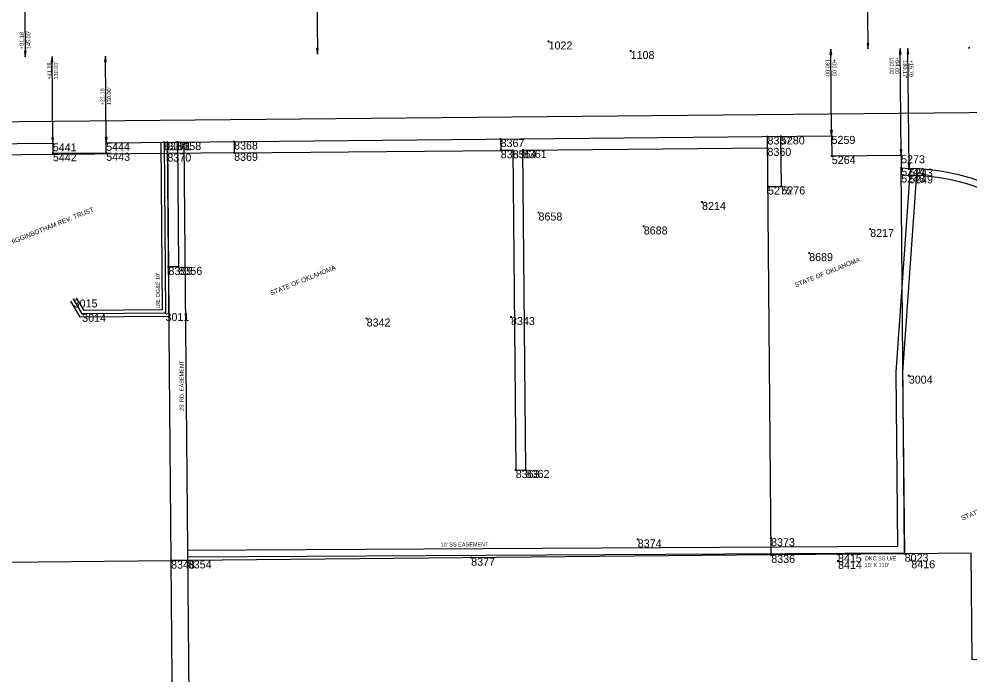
# Model space of a CAD drawing. Extents: x 2145146 to 2158053, y 137507 to 150829.
# Drawn here: x 2148600 to 2150026, y 142146 to 143129 of the extents above; entities that cross this region are included whole.
import ezdxf

# ---------------------------------------------------------------- set-up
doc = ezdxf.new("R2010")
doc.units = 0
for name, color, linetype in [('ALIGN_Cogo Points', 7, 'Continuous'), ('ALIGN_ROW Dimension', 7, 'Continuous'), ('ALIGN_ROW Line', 7, 'Continuous'), ('PLSS_Easement', 7, 'Continuous'), ('PLSS_Property Line', 7, 'Continuous'), ('PLSS_Section Line', 7, 'Continuous'), ('PLSS_Text', 7, 'Continuous'), ('PLSS_Text_TURNED OFF', 7, 'Continuous')]:
    doc.layers.add(name, color=color, linetype=linetype)

# ---------------------------------------------------------------- blocks, each defined once
blk = doc.blocks.new('Arrowhd')
at = {"layer": 'PLSS_Property Line'}
blk.add_lwpolyline([(0.125, -0.021), (0.125, 0.021), (0, 0)], close=True, dxfattribs=at)

msp = doc.modelspace()

# ---------------------------------------------------------------- linework, layer by layer
at = {"layer": 'ALIGN_Cogo Points'}
for points in [[(2149393.7, 143095.3), (2149393.7, 143096.5), (2149393.7, 143095.3), (2149392.5, 143095.3), (2149393.7, 143095.3), (2149393.7, 143094.1), (2149393.7, 143095.3), (2149394.9, 143095.3)], [(2149516.8, 143081), (2149516.8, 143082.2), (2149516.8, 143081), (2149515.6, 143081), (2149516.8, 143081), (2149516.8, 143079.8), (2149516.8, 143081), (2149518, 143081)], [(2150024.3, 143085.8), (2150024.3, 143087), (2150024.3, 143085.8), (2150023.1, 143085.8), (2150024.3, 143085.8), (2150024.3, 143084.6), (2150024.3, 143085.8), (2150025.5, 143085.8)], [(2149321.7, 142949.1), (2149321.7, 142950.3), (2149321.7, 142949.1), (2149320.5, 142949.1), (2149321.7, 142949.1), (2149321.7, 142947.9), (2149321.7, 142949.1), (2149322.9, 142949.1)], [(2149722, 142952.9), (2149722, 142954.1), (2149722, 142952.9), (2149720.8, 142952.9), (2149722, 142952.9), (2149722, 142951.7), (2149722, 142952.9), (2149723.2, 142952.9)], [(2149742, 142953.1), (2149742, 142954.3), (2149742, 142953.1), (2149740.8, 142953.1), (2149742, 142953.1), (2149742, 142951.9), (2149742, 142953.1), (2149743.2, 142953.1)], [(2149818, 142953.8), (2149818, 142955), (2149818, 142953.8), (2149816.8, 142953.8), (2149818, 142953.8), (2149818, 142952.6), (2149818, 142953.8), (2149819.2, 142953.8)], [(2148650.3, 142942.7), (2148650.3, 142943.9), (2148650.3, 142942.7), (2148649.1, 142942.7), (2148650.3, 142942.7), (2148650.3, 142941.5), (2148650.3, 142942.7), (2148651.5, 142942.7)], [(2148730.3, 142943.5), (2148730.3, 142944.7), (2148730.3, 142943.5), (2148729.1, 142943.5), (2148730.3, 142943.5), (2148730.3, 142942.3), (2148730.3, 142943.5), (2148731.5, 142943.5)], [(2148817.1, 142944.4), (2148817.1, 142945.6), (2148817.1, 142944.4), (2148815.9, 142944.4), (2148817.1, 142944.4), (2148817.1, 142943.2), (2148817.1, 142944.4), (2148818.3, 142944.4)], [(2148822.1, 142944.4), (2148822.1, 142945.6), (2148822.1, 142944.4), (2148820.9, 142944.4), (2148822.1, 142944.4), (2148822.1, 142943.2), (2148822.1, 142944.4), (2148823.3, 142944.4)], [(2148837.1, 142944.6), (2148837.1, 142945.8), (2148837.1, 142944.6), (2148835.9, 142944.6), (2148837.1, 142944.6), (2148837.1, 142943.4), (2148837.1, 142944.6), (2148838.3, 142944.6)], [(2148922.1, 142945.4), (2148922.1, 142946.6), (2148922.1, 142945.4), (2148920.9, 142945.4), (2148922.1, 142945.4), (2148922.1, 142944.2), (2148922.1, 142945.4), (2148923.3, 142945.4)], [(2149321.9, 142932.2), (2149321.9, 142933.4), (2149321.9, 142932.2), (2149320.7, 142932.2), (2149321.9, 142932.2), (2149321.9, 142931), (2149321.9, 142932.2), (2149323.1, 142932.2)], [(2149340.1, 142932.3), (2149340.1, 142933.5), (2149340.1, 142932.3), (2149338.9, 142932.3), (2149340.1, 142932.3), (2149340.1, 142931.1), (2149340.1, 142932.3), (2149341.3, 142932.3)], [(2149355.1, 142932.5), (2149355.1, 142933.7), (2149355.1, 142932.5), (2149353.9, 142932.5), (2149355.1, 142932.5), (2149355.1, 142931.3), (2149355.1, 142932.5), (2149356.3, 142932.5)], [(2149721.9, 142935.9), (2149721.9, 142937.1), (2149721.9, 142935.9), (2149720.7, 142935.9), (2149721.9, 142935.9), (2149721.9, 142934.7), (2149721.9, 142935.9), (2149723.1, 142935.9)], [(2148650.5, 142927.7), (2148650.5, 142928.9), (2148650.5, 142927.7), (2148649.3, 142927.7), (2148650.5, 142927.7), (2148650.5, 142926.5), (2148650.5, 142927.7), (2148651.7, 142927.7)], [(2148730.4, 142928.5), (2148730.4, 142929.7), (2148730.4, 142928.5), (2148729.2, 142928.5), (2148730.4, 142928.5), (2148730.4, 142927.3), (2148730.4, 142928.5), (2148731.6, 142928.5)], [(2148822.2, 142927.4), (2148822.2, 142928.6), (2148822.2, 142927.4), (2148821, 142927.4), (2148822.2, 142927.4), (2148822.2, 142926.2), (2148822.2, 142927.4), (2148823.4, 142927.4)], [(2148922.2, 142928.4), (2148922.2, 142929.6), (2148922.2, 142928.4), (2148921, 142928.4), (2148922.2, 142928.4), (2148922.2, 142927.2), (2148922.2, 142928.4), (2148923.4, 142928.4)], [(2149818.3, 142923.8), (2149818.3, 142925), (2149818.3, 142923.8), (2149817.1, 142923.8), (2149818.3, 142923.8), (2149818.3, 142922.6), (2149818.3, 142923.8), (2149819.5, 142923.8)], [(2149922.3, 142924.8), (2149922.3, 142926), (2149922.3, 142924.8), (2149921.1, 142924.8), (2149922.3, 142924.8), (2149922.3, 142923.6), (2149922.3, 142924.8), (2149923.5, 142924.8)], [(2149922.4, 142905.9), (2149922.4, 142907.1), (2149922.4, 142905.9), (2149921.2, 142905.9), (2149922.4, 142905.9), (2149922.4, 142904.7), (2149922.4, 142905.9), (2149923.6, 142905.9)], [(2149934.2, 142904.7), (2149934.2, 142905.9), (2149934.2, 142904.7), (2149933, 142904.7), (2149934.2, 142904.7), (2149934.2, 142903.5), (2149934.2, 142904.7), (2149935.4, 142904.7)], [(2149922.5, 142895.9), (2149922.5, 142897.1), (2149922.5, 142895.9), (2149921.3, 142895.9), (2149922.5, 142895.9), (2149922.5, 142894.7), (2149922.5, 142895.9), (2149923.7, 142895.9)], [(2149934.3, 142894.7), (2149934.3, 142895.9), (2149934.3, 142894.7), (2149933.1, 142894.7), (2149934.3, 142894.7), (2149934.3, 142893.5), (2149934.3, 142894.7), (2149935.5, 142894.7)], [(2149722.7, 142877.9), (2149722.7, 142879.1), (2149722.7, 142877.9), (2149721.5, 142877.9), (2149722.7, 142877.9), (2149722.7, 142876.7), (2149722.7, 142877.9), (2149723.9, 142877.9)], [(2149742.7, 142878.1), (2149742.7, 142879.3), (2149742.7, 142878.1), (2149741.5, 142878.1), (2149742.7, 142878.1), (2149742.7, 142876.9), (2149742.7, 142878.1), (2149743.9, 142878.1)], [(2149623.8, 142854.8), (2149623.8, 142856), (2149623.8, 142854.8), (2149622.6, 142854.8), (2149623.8, 142854.8), (2149623.8, 142853.6), (2149623.8, 142854.8), (2149625, 142854.8)], [(2149378.6, 142839), (2149378.6, 142840.2), (2149378.6, 142839), (2149377.4, 142839), (2149378.6, 142839), (2149378.6, 142837.8), (2149378.6, 142839), (2149379.8, 142839)], [(2149536.4, 142818.1), (2149536.4, 142819.3), (2149536.4, 142818.1), (2149535.2, 142818.1), (2149536.4, 142818.1), (2149536.4, 142816.9), (2149536.4, 142818.1), (2149537.6, 142818.1)], [(2149875.9, 142814.3), (2149875.9, 142815.5), (2149875.9, 142814.3), (2149874.7, 142814.3), (2149875.9, 142814.3), (2149875.9, 142813.1), (2149875.9, 142814.3), (2149877.1, 142814.3)], [(2149784.4, 142778.2), (2149784.4, 142779.4), (2149784.4, 142778.2), (2149783.2, 142778.2), (2149784.4, 142778.2), (2149784.4, 142777), (2149784.4, 142778.2), (2149785.6, 142778.2)], [(2148823.7, 142757.4), (2148823.7, 142758.6), (2148823.7, 142757.4), (2148822.5, 142757.4), (2148823.7, 142757.4), (2148823.7, 142756.2), (2148823.7, 142757.4), (2148824.9, 142757.4)], [(2148838.7, 142757.6), (2148838.7, 142758.8), (2148838.7, 142757.6), (2148837.5, 142757.6), (2148838.7, 142757.6), (2148838.7, 142756.4), (2148838.7, 142757.6), (2148839.9, 142757.6)], [(2148681.6, 142708.7), (2148681.6, 142709.9), (2148681.6, 142708.7), (2148680.4, 142708.7), (2148681.6, 142708.7), (2148681.6, 142707.5), (2148681.6, 142708.7), (2148682.8, 142708.7)], [(2148694.4, 142687.2), (2148694.4, 142688.4), (2148694.4, 142687.2), (2148693.2, 142687.2), (2148694.4, 142687.2), (2148694.4, 142686), (2148694.4, 142687.2), (2148695.6, 142687.2)], [(2148819.3, 142688.4), (2148819.3, 142689.6), (2148819.3, 142688.4), (2148818.1, 142688.4), (2148819.3, 142688.4), (2148819.3, 142687.2), (2148819.3, 142688.4), (2148820.5, 142688.4)], [(2149120.9, 142680.2), (2149120.9, 142681.4), (2149120.9, 142680.2), (2149119.7, 142680.2), (2149120.9, 142680.2), (2149120.9, 142679), (2149120.9, 142680.2), (2149122.1, 142680.2)], [(2149337.4, 142682.3), (2149337.4, 142683.5), (2149337.4, 142682.3), (2149336.2, 142682.3), (2149337.4, 142682.3), (2149337.4, 142681.1), (2149337.4, 142682.3), (2149338.6, 142682.3)], [(2149933.8, 142594.6), (2149933.8, 142595.8), (2149933.8, 142594.6), (2149932.6, 142594.6), (2149933.8, 142594.6), (2149933.8, 142593.4), (2149933.8, 142594.6), (2149935, 142594.6)], [(2149344.4, 142453.1), (2149344.4, 142454.3), (2149344.4, 142453.1), (2149343.2, 142453.1), (2149344.4, 142453.1), (2149344.4, 142451.9), (2149344.4, 142453.1), (2149345.6, 142453.1)], [(2149359.4, 142453.3), (2149359.4, 142454.5), (2149359.4, 142453.3), (2149358.2, 142453.3), (2149359.4, 142453.3), (2149359.4, 142452.1), (2149359.4, 142453.3), (2149360.6, 142453.3)], [(2149527.4, 142349.1), (2149527.4, 142350.3), (2149527.4, 142349.1), (2149526.2, 142349.1), (2149527.4, 142349.1), (2149527.4, 142347.9), (2149527.4, 142349.1), (2149528.6, 142349.1)], [(2149727.3, 142351), (2149727.3, 142352.2), (2149727.3, 142351), (2149726.1, 142351), (2149727.3, 142351), (2149727.3, 142349.8), (2149727.3, 142351), (2149728.5, 142351)], [(2149277.6, 142321.7), (2149277.6, 142322.9), (2149277.6, 142321.7), (2149276.4, 142321.7), (2149277.6, 142321.7), (2149277.6, 142320.5), (2149277.6, 142321.7), (2149278.8, 142321.7)], [(2149727.6, 142326), (2149727.6, 142327.2), (2149727.6, 142326), (2149726.4, 142326), (2149727.6, 142326), (2149727.6, 142324.8), (2149727.6, 142326), (2149728.8, 142326)], [(2149827.6, 142326.9), (2149827.6, 142328.1), (2149827.6, 142326.9), (2149826.4, 142326.9), (2149827.6, 142326.9), (2149827.6, 142325.7), (2149827.6, 142326.9), (2149828.8, 142326.9)], [(2149927.6, 142327.8), (2149927.6, 142329), (2149927.6, 142327.8), (2149926.4, 142327.8), (2149927.6, 142327.8), (2149927.6, 142326.6), (2149927.6, 142327.8), (2149928.8, 142327.8)], [(2148827.7, 142317.4), (2148827.7, 142318.6), (2148827.7, 142317.4), (2148826.5, 142317.4), (2148827.7, 142317.4), (2148827.7, 142316.2), (2148827.7, 142317.4), (2148828.9, 142317.4)], [(2148852.7, 142317.7), (2148852.7, 142318.9), (2148852.7, 142317.7), (2148851.5, 142317.7), (2148852.7, 142317.7), (2148852.7, 142316.5), (2148852.7, 142317.7), (2148853.9, 142317.7)], [(2149827.7, 142316.9), (2149827.7, 142318.1), (2149827.7, 142316.9), (2149826.5, 142316.9), (2149827.7, 142316.9), (2149827.7, 142315.7), (2149827.7, 142316.9), (2149828.9, 142316.9)], [(2149937.6, 142317.9), (2149937.6, 142319.1), (2149937.6, 142317.9), (2149936.4, 142317.9), (2149937.6, 142317.9), (2149937.6, 142316.7), (2149937.6, 142317.9), (2149938.8, 142317.9)]]:
    msp.add_lwpolyline(points, dxfattribs=at)
at = {"layer": 'ALIGN_ROW Dimension'}
for points in [[(2149868, 143567.3), (2149872.6, 143084.3)], [(2149045.2, 143275.5), (2149047.1, 143076.5)], [(2148607.7, 143217.4), (2148609.1, 143072.4)], [(2149818, 142953.8), (2149816.8, 143083.8)], [(2149922.3, 142924.8), (2149920.8, 143084.8)], [(2149934.2, 142904.7), (2149932.5, 143084.9)], [(2148650.3, 142942.7), (2148649.1, 143072.7)], [(2148730.3, 142943.5), (2148729.1, 143073.5)]]:
    msp.add_lwpolyline(points, dxfattribs=at)
at = {"layer": 'ALIGN_ROW Line'}
msp.add_lwpolyline([(2148049.2, 142700.1), (2148047.3, 142920.1), (2148122.2, 142920.8), (2148222.2, 142921.7), (2148222.1, 142938.7), (2148650.3, 142942.7), (2148650.5, 142927.7), (2148730.4, 142928.5), (2148730.3, 142943.5), (2149818, 142953.8), (2149818.3, 142923.8), (2149922.3, 142924.8), (2149922.4, 142905.9), (2149934.2, 142904.7)], dxfattribs=at)
msp.add_arc((2149933.8, 142594.6), 310.1, 43.3958, 89.9357, dxfattribs=at)
at = {"layer": 'PLSS_Easement'}
for points in [[(2149321.7, 142949.1), (2149321.9, 142932.2), (2149340.1, 142932.3), (2149344.4, 142453.1), (2149359.4, 142453.3), (2149355.1, 142932.5), (2149721.9, 142935.9), (2149722, 142952.9)], [(2149722.7, 142877.9), (2149742.7, 142878.1), (2149742, 142953.1)], [(2148822.1, 142944.4), (2148824.4, 142683.4), (2148691.5, 142682.2), (2148677.3, 142706.2)], [(2148817.1, 142944.4), (2148819.3, 142688.4), (2148694.4, 142687.2), (2148681.6, 142708.7)], [(2148812.1, 142944.3), (2148814.3, 142693.3), (2148697.2, 142692.2), (2148686, 142711.3)], [(2148922.1, 142945.3), (2148922.2, 142928.4), (2148822.2, 142927.4)], [(2148837.1, 142944.5), (2148838.7, 142757.6), (2148823.7, 142757.4)], [(2148847, 142944.5), (2148858.4, 141667.7)], [(2148822.2, 142927.4), (2148222.2, 142921.7)], [(2148922.2, 142928.4), (2149321.9, 142932.1)], [(2149935.8, 142904.5), (2149914.3, 142599.9), (2149917.1, 142338.7), (2148851.6, 142332.6)], [(2149922.4, 142905.9), (2149922.5, 142895.9), (2149934.3, 142894.7)], [(2149945.8, 142903.8), (2149924.3, 142599.6), (2149927.2, 142328.8), (2148851.7, 142322.6)], [(2148833.4, 141667.5), (2148827.7, 142317.4)]]:
    msp.add_lwpolyline(points, dxfattribs=at)
msp.add_arc((2149933.8, 142594.6), 300.1, 43.4233, 89.9173, dxfattribs=at)
at = {"layer": 'PLSS_Property Line'}
for points in [[(2149927.6, 142327.8), (2149727.6, 142326), (2149722, 142952.9)], [(2148522.1, 142941.6), (2148528, 142314.6), (2148827.7, 142317.4)], [(2149727.6, 142326), (2148852.7, 142317.7), (2148827.7, 142317.4), (2148822.1, 142944.4)], [(2150424, 142172.5), (2150029, 142168.8), (2150027.5, 142328.8), (2149927.6, 142327.8), (2149922.4, 142907.1)]]:
    msp.add_lwpolyline(points, dxfattribs=at)
at = {"layer": 'PLSS_Section Line'}
msp.add_lwpolyline([(2148283.1, 142972.3), (2150921.7, 142997.3)], dxfattribs=at)

# ---------------------------------------------------------------- block references
at = {"layer": 'ALIGN_ROW Dimension'}
for p, xscale, yscale, rotation in [((2149872.6, 143084.3), 65, 65, 90), ((2148609.1, 143072.4), 65, 65, 90.54769354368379), ((2149047.1, 143076.5), 64.99999999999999, 65, 90.54090497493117), ((2149816.8, 143083.8), 65, 65, -89.5450070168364), ((2149920.8, 143084.8), 65, 65, -89.5450070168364), ((2149932.5, 143084.9), 65, 65, -89.5450070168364), ((2148649.1, 143072.7), 65, 65, -89.5450070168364), ((2148729.1, 143073.5), 65, 65, -89.5450070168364), ((2149818, 142953.9), 65, 64.99999999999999, 90.5463123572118), ((2148650.3, 142942.8), 65, 64.99999999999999, 90.5463123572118), ((2148730.3, 142943.5), 65, 64.99999999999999, 90.5463123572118), ((2149922.3, 142924.8), 65, 64.99999999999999, 90.5463123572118), ((2149934.2, 142904.7), 65, 64.99999999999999, 90.5463123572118)]:
    msp.add_blockref('Arrowhd', p, dxfattribs=dict(at, xscale=xscale, yscale=yscale, rotation=rotation))

# ---------------------------------------------------------------- texts
at = {"layer": 'ALIGN_Cogo Points'}
for s, p in [('1022', (2149393.7, 143083.3)), ('1108', (2149516.8, 143069)), ('8367', (2149321.7, 142937.1)), ('8337', (2149722, 142940.9)), ('5280', (2149742, 142941.1)), ('5259', (2149818, 142941.8)), ('5441', (2148650.3, 142930.7)), ('5444', (2148730.3, 142931.5)), ('8384', (2148817.1, 142932.4)), ('8371', (2148822.1, 142932.4)), ('8358', (2148837.1, 142932.6)), ('8368', (2148922.1, 142933.4)), ('8360', (2149721.9, 142923.9)), ('5442', (2148650.5, 142915.7)), ('5443', (2148730.4, 142916.5)), ('8370', (2148822.2, 142915.4)), ('8369', (2148922.2, 142916.4)), ('8365', (2149321.9, 142920.2)), ('8364', (2149340.1, 142920.3)), ('8361', (2149355.1, 142920.5)), ('5264', (2149818.3, 142911.8)), ('5273', (2149922.3, 142912.8)), ('5244', (2149922.4, 142893.9)), ('5243', (2149934.2, 142892.7)), ('5248', (2149922.5, 142883.9)), ('5249', (2149934.3, 142882.7)), ('5275', (2149722.7, 142865.9)), ('5276', (2149742.7, 142866.1)), ('8214', (2149623.8, 142842.8)), ('8658', (2149378.6, 142827)), ('8688', (2149536.4, 142806.1)), ('8217', (2149875.9, 142802.3)), ('8689', (2149784.4, 142766.2)), ('8355', (2148823.7, 142745.4)), ('8356', (2148838.7, 142745.6)), ('3015', (2148681.6, 142696.7)), ('3014', (2148694.4, 142675.2)), ('3011', (2148819.3, 142676.4)), ('8342', (2149120.9, 142668.2)), ('8343', (2149337.4, 142670.3)), ('3004', (2149933.8, 142582.6)), ('8363', (2149344.4, 142441.1)), ('8362', (2149359.4, 142441.3)), ('8374', (2149527.4, 142337.1)), ('8373', (2149727.3, 142339)), ('8377', (2149277.6, 142309.7)), ('8336', (2149727.6, 142314)), ('8415', (2149827.6, 142314.9)), ('8023', (2149927.6, 142315.8)), ('8348', (2148827.7, 142305.4)), ('8354', (2148852.7, 142305.7)), ('8414', (2149827.7, 142304.9)), ('8416', (2149937.6, 142305.9))]:
    msp.add_text(s, height=12, dxfattribs=at).set_placement(p)
at = {"layer": 'ALIGN_ROW Dimension'}
for s, rotation, p in [('+01.18', 90.3083, (2148606.6, 143083.8)), ("145.00'", 90.3083, (2148616.8, 143083.8)), ('+41.18', 90.3083, (2148648.1, 143038.2)), ("130.00'", 90.3083, (2148658.2, 143038.3)), ("130.00'", 270.3083, (2149809, 143068.9)), ('+00.00', 270.3083, (2149819.2, 143069)), ("160.00'", 270.3083, (2149905.2, 143071.8)), ('+04.00', 270.3083, (2149913.3, 143072.1)), ("180.17'", 270.3083, (2149925, 143067.1)), ('+15.70', 270.3083, (2149934.5, 143067.8)), ('+21.18', 90.3083, (2148727.6, 142999.5)), ("130.00'", 90.3083, (2148737.8, 142999.6))]:
    msp.add_text(s, height=6, rotation=rotation, dxfattribs=at).set_placement(p)
at = {"layer": 'PLSS_Text'}
for s, rotation, p in [(" U/E OG&E 10'", 90.3221, (2148811, 142693.3)), ("25' RD. EASEMENT", 90, (2148846.5, 142541.8)), ("10' SS EASEMENT ", 0.4664, (2149231.7, 142338.3))]:
    msp.add_text(s, height=6, rotation=rotation, dxfattribs=at).set_placement(p)
for s, p in [('OKC SS U/E', (2149867.5, 142317.7)), ("10' X 110'", (2149867.5, 142307.7))]:
    msp.add_text(s, height=6, dxfattribs=at).set_placement(p)
at = {"layer": 'PLSS_Text_TURNED OFF'}
for s, p in [('W.W. HIGGINBOTHAM REV. TRUST', (2148562, 142780.2)), ('STATE OF OKLAHOMA', (2149764.4, 142726.6)), ('STATE OF OKLAHOMA', (2148978, 142714.8)), ('STATE OF OKLAHOMA', (2150014, 142377.5))]:
    msp.add_text(s, height=7, rotation=22, dxfattribs=at).set_placement(p)

doc.saveas('drawing.dxf')
